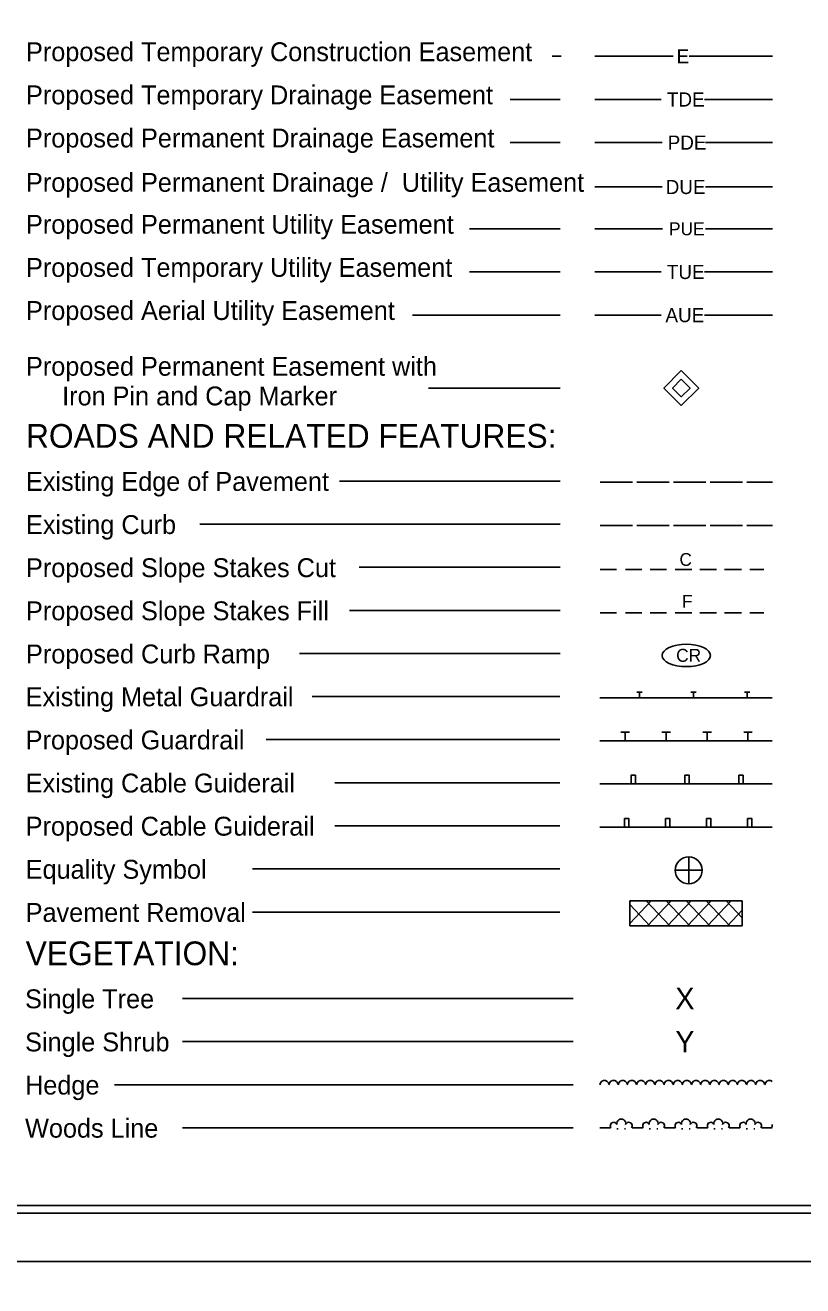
# Model space of a CAD drawing. Extents: x 1664524 to 1666208, y 587901 to 592296.
# Drawn here: x 1665085 to 1665446, y 588990 to 589575 of the extents above; entities that cross this region are included whole.
import ezdxf

# ---------------------------------------------------------------- set-up
doc = ezdxf.new("R2010")
doc.units = 0
for name, color, linetype in [('Prop Easement Permanent Drainage Utility', 7, 'Continuous'), ('Prop Horizontal Alignment Tick Large', 7, 'Continuous'), ('Prop Horizontal Alignment Tick Small', 7, 'Continuous'), ('Prop ROW Permanent Easement CELL', 7, 'Continuous'), ('Prop WCC CELL', 7, 'Continuous'), ('Sheet Cutting Line CELL', 7, 'Continuous'), ('Sheet Symbology CELL', 7, 'Continuous')]:
    doc.layers.add(name, color=color, linetype=linetype)

msp = doc.modelspace()

# ---------------------------------------------------------------- linework, layer by layer
at = {"layer": 'Prop Easement Permanent Drainage Utility'}
for p, q in [((1665349.26, 589499.7), (1665380.56, 589499.7)), ((1665400.56, 589499.7), (1665431.76, 589499.7))]:
    msp.add_line(p, q, dxfattribs=at)
at = {"layer": 'Prop Horizontal Alignment Tick Large'}
msp.add_lwpolyline([(1664536.76, 589023.8), (1666203.26, 589023.8), (1666203.26, 590078.9), (1664536.76, 590078.9)], close=True, dxfattribs=at)
at = {"layer": 'Prop Horizontal Alignment Tick Small'}
for points in [[(1664523.76, 589001.35), (1666207.76, 589001.35), (1666207.76, 590101.35), (1664523.76, 590101.35)], [(1666207.76, 589001.35), (1664523.76, 589001.35), (1664523.76, 587901.35), (1666207.76, 587901.35)]]:
    msp.add_lwpolyline(points, close=True, dxfattribs=at)
at = {"layer": 'Prop ROW Permanent Easement CELL'}
msp.add_line((1665389.4, 589406.46), (1665389.4, 589406.46), dxfattribs=at)
for points in [[(1665389.4, 589414.51), (1665397.46, 589406.45), (1665389.4, 589398.4), (1665381.35, 589406.45)], [(1665389.4, 589410.48), (1665393.43, 589406.45), (1665389.4, 589402.43), (1665385.38, 589406.45)]]:
    msp.add_lwpolyline(points, close=True, dxfattribs=at)
at = {"layer": 'Prop WCC CELL'}
msp.add_ellipse((1665391.72, 589282.43), major_axis=(11.21, 0), ratio=0.462467, dxfattribs=at)
at = {"layer": 'Sheet Cutting Line CELL'}
for p, q in [((1664523.76, 589001.35), (1666207.76, 589001.35)), ((1666207.76, 589001.35), (1664523.76, 589001.35))]:
    msp.add_line(p, q, dxfattribs=at)
at = {"layer": 'Sheet Symbology CELL'}
for p, q in [((1665333.61, 589560.29), (1665329.44, 589560.29)), ((1665349.26, 589560.29), (1665351.87, 589560.29)), ((1665351.87, 589560.29), (1665385.62, 589560.29)), ((1665393.12, 589560.29), (1665426.87, 589560.29)), ((1665426.87, 589560.29), (1665431.76, 589560.29)), ((1665333.23, 589540.29), (1665310.08, 589540.29)), ((1665349.26, 589540.29), (1665352.61, 589540.29)), ((1665352.61, 589540.29), (1665380.11, 589540.29)), ((1665400.11, 589540.29), (1665427.61, 589540.29)), ((1665427.61, 589540.29), (1665431.76, 589540.29)), ((1665333.23, 589520.29), (1665310.08, 589520.29)), ((1665349.26, 589520.29), (1665353.06, 589520.29)), ((1665353.06, 589520.29), (1665380.56, 589520.29)), ((1665400.56, 589520.29), (1665428.06, 589520.29)), ((1665428.06, 589520.29), (1665431.76, 589520.29)), ((1665333.23, 589480.28), (1665291.09, 589480.28)), ((1665349.26, 589480.28), (1665353.1, 589480.28)), ((1665353.1, 589480.28), (1665380.6, 589480.28)), ((1665400.6, 589480.28), (1665428.1, 589480.28)), ((1665428.1, 589480.28), (1665431.76, 589480.28)), ((1665333.23, 589460.28), (1665291.09, 589460.28)), ((1665349.26, 589460.28), (1665352.61, 589460.28)), ((1665352.61, 589460.28), (1665380.11, 589460.28)), ((1665400.11, 589460.28), (1665427.61, 589460.28)), ((1665427.61, 589460.28), (1665431.76, 589460.28)), ((1665333.23, 589440.28), (1665264.77, 589440.28)), ((1665349.26, 589440.28), (1665352.61, 589440.28)), ((1665352.61, 589440.28), (1665380.11, 589440.28)), ((1665400.11, 589440.28), (1665427.61, 589440.28)), ((1665427.61, 589440.28), (1665431.76, 589440.28)), ((1665333.23, 589406.45), (1665272.22, 589406.45)), ((1665333.23, 589363.3), (1665230.88, 589363.3)), ((1665351.76, 589362.72), (1665366.76, 589362.72)), ((1665368.76, 589362.72), (1665383.76, 589362.72)), ((1665385.76, 589362.72), (1665400.76, 589362.72)), ((1665402.76, 589362.72), (1665417.76, 589362.72)), ((1665419.76, 589362.72), (1665431.76, 589362.72)), ((1665333.23, 589343.3), (1665166.08, 589343.3)), ((1665351.76, 589342.72), (1665366.76, 589342.72)), ((1665368.76, 589342.72), (1665383.76, 589342.72)), ((1665385.76, 589342.72), (1665400.76, 589342.72)), ((1665402.76, 589342.72), (1665417.76, 589342.72)), ((1665419.76, 589342.72), (1665431.76, 589342.72)), ((1665333.23, 589323.3), (1665240.04, 589323.3)), ((1665351.76, 589322.25), (1665359.36, 589322.25)), ((1665371.06, 589322.25), (1665363.51, 589322.25)), ((1665382.56, 589322.25), (1665374.96, 589322.25)), ((1665394.31, 589322.25), (1665386.51, 589322.25)), ((1665405.76, 589322.25), (1665398.01, 589322.25)), ((1665417.31, 589322.25), (1665409.46, 589322.25)), ((1665427.61, 589322.25), (1665421.21, 589322.25)), ((1665333.23, 589303.3), (1665235.49, 589303.3)), ((1665351.76, 589302.25), (1665359.36, 589302.25)), ((1665371.06, 589302.25), (1665363.51, 589302.25)), ((1665382.56, 589302.25), (1665374.96, 589302.25)), ((1665394.31, 589302.25), (1665386.51, 589302.25)), ((1665405.76, 589302.25), (1665398.01, 589302.25)), ((1665417.31, 589302.25), (1665409.46, 589302.25)), ((1665427.61, 589302.25), (1665421.21, 589302.25)), ((1665333.23, 589283.3), (1665212.3, 589283.3)), ((1665333.07, 589263.42), (1665218.23, 589263.42)), ((1665351.6, 589262.84), (1665431.6, 589262.84)), ((1665368.74, 589265.34), (1665371.24, 589265.34)), ((1665369.99, 589262.84), (1665369.99, 589265.34)), ((1665393.74, 589265.34), (1665396.24, 589265.34)), ((1665394.99, 589262.84), (1665394.99, 589265.34)), ((1665418.74, 589265.34), (1665421.24, 589265.34)), ((1665419.99, 589262.84), (1665419.99, 589265.34)), ((1665333.07, 589243.42), (1665196.83, 589243.42)), ((1665431.6, 589242.84), (1665351.6, 589242.84)), ((1665361.33, 589246.79), (1665365.33, 589246.79)), ((1665363.33, 589242.84), (1665363.33, 589246.79)), ((1665380.33, 589246.79), (1665384.33, 589246.79)), ((1665382.33, 589242.84), (1665382.33, 589246.79)), ((1665399.33, 589246.79), (1665403.33, 589246.79)), ((1665401.33, 589242.84), (1665401.33, 589246.79)), ((1665418.33, 589246.79), (1665422.33, 589246.79)), ((1665420.33, 589242.84), (1665420.33, 589246.79)), ((1665333.07, 589223.42), (1665228.77, 589223.42)), ((1665351.6, 589222.84), (1665431.6, 589222.84)), ((1665333.07, 589203.42), (1665228.77, 589203.42)), ((1665351.6, 589202.84), (1665431.6, 589202.84)), ((1665392.83, 589189.08), (1665392.83, 589182.83)), ((1665333.07, 589183.42), (1665190.45, 589183.42)), ((1665386.58, 589182.83), (1665392.83, 589182.83)), ((1665392.83, 589182.83), (1665392.83, 589176.58)), ((1665392.83, 589182.83), (1665399.08, 589182.83)), ((1665365.55, 589168.7), (1665417.65, 589168.7)), ((1665365.55, 589157), (1665365.55, 589168.7)), ((1665365.55, 589168.1), (1665366.1, 589168.7)), ((1665365.55, 589158.15), (1665375.4, 589168.7)), ((1665374.8, 589157), (1665365.55, 589166.9)), ((1665384.1, 589157), (1665373.1, 589168.7)), ((1665373.7, 589157), (1665384.7, 589168.7)), ((1665393.35, 589157), (1665382.4, 589168.7)), ((1665382.95, 589157), (1665394, 589168.7)), ((1665402.65, 589157), (1665391.65, 589168.7)), ((1665392.25, 589157), (1665403.25, 589168.7)), ((1665411.95, 589157), (1665400.9, 589168.7)), ((1665401.55, 589157), (1665412.5, 589168.7)), ((1665417.65, 589160.75), (1665410.2, 589168.7)), ((1665417.65, 589168.7), (1665417.65, 589157)), ((1665333.07, 589163.42), (1665190.45, 589163.42)), ((1665410.8, 589157), (1665417.65, 589164.3)), ((1665417.65, 589157), (1665365.55, 589157)), ((1665339.21, 589123.35), (1665158.08, 589123.35)), ((1665339.21, 589103.35), (1665158.08, 589103.35)), ((1665351.9, 589084.3), (1665352.5, 589084.95)), ((1665352.5, 589084.95), (1665353.3, 589085.4)), ((1665353.3, 589085.4), (1665354.25, 589085.4)), ((1665354.25, 589085.4), (1665355.05, 589084.9)), ((1665355.05, 589084.9), (1665355.6, 589084.25)), ((1665356.15, 589084.3), (1665356.75, 589084.95)), ((1665356.75, 589084.95), (1665357.55, 589085.4)), ((1665357.55, 589085.4), (1665358.5, 589085.4)), ((1665358.5, 589085.4), (1665359.3, 589084.9)), ((1665359.3, 589084.9), (1665359.85, 589084.25)), ((1665360.4, 589084.3), (1665361, 589084.95)), ((1665361, 589084.95), (1665361.8, 589085.4)), ((1665361.8, 589085.4), (1665362.75, 589085.4)), ((1665362.75, 589085.4), (1665363.55, 589084.9)), ((1665363.55, 589084.9), (1665364.1, 589084.25)), ((1665364.65, 589084.3), (1665365.25, 589084.95)), ((1665365.25, 589084.95), (1665366.05, 589085.4)), ((1665366.05, 589085.4), (1665367, 589085.4)), ((1665367, 589085.4), (1665367.8, 589084.9)), ((1665367.8, 589084.9), (1665368.35, 589084.25)), ((1665368.9, 589084.3), (1665369.5, 589084.95)), ((1665369.5, 589084.95), (1665370.3, 589085.4)), ((1665370.3, 589085.4), (1665371.25, 589085.4)), ((1665371.25, 589085.4), (1665372.05, 589084.9)), ((1665372.05, 589084.9), (1665372.6, 589084.25)), ((1665373.15, 589084.3), (1665373.75, 589084.95)), ((1665373.75, 589084.95), (1665374.55, 589085.4)), ((1665374.55, 589085.4), (1665375.5, 589085.4)), ((1665375.5, 589085.4), (1665376.3, 589084.9)), ((1665376.3, 589084.9), (1665376.85, 589084.25)), ((1665377.4, 589084.3), (1665378, 589084.95)), ((1665378, 589084.95), (1665378.8, 589085.4)), ((1665378.8, 589085.4), (1665379.75, 589085.4)), ((1665379.75, 589085.4), (1665380.55, 589084.9)), ((1665380.55, 589084.9), (1665381.1, 589084.25)), ((1665381.65, 589084.3), (1665382.25, 589084.95)), ((1665382.25, 589084.95), (1665383.05, 589085.4)), ((1665383.05, 589085.4), (1665384, 589085.4)), ((1665384, 589085.4), (1665384.8, 589084.9)), ((1665384.8, 589084.9), (1665385.35, 589084.25)), ((1665385.9, 589084.3), (1665386.5, 589084.95)), ((1665386.5, 589084.95), (1665387.3, 589085.4)), ((1665387.3, 589085.4), (1665388.25, 589085.4)), ((1665388.25, 589085.4), (1665389.05, 589084.9)), ((1665389.05, 589084.9), (1665389.6, 589084.25)), ((1665390.15, 589084.3), (1665390.75, 589084.95)), ((1665390.75, 589084.95), (1665391.55, 589085.4)), ((1665391.55, 589085.4), (1665392.5, 589085.4)), ((1665392.5, 589085.4), (1665393.3, 589084.9)), ((1665393.3, 589084.9), (1665393.85, 589084.25)), ((1665394.4, 589084.3), (1665395, 589084.95)), ((1665395, 589084.95), (1665395.8, 589085.4)), ((1665395.8, 589085.4), (1665396.75, 589085.4)), ((1665396.75, 589085.4), (1665397.55, 589084.9)), ((1665397.55, 589084.9), (1665398.1, 589084.25)), ((1665398.65, 589084.3), (1665399.25, 589084.95)), ((1665399.25, 589084.95), (1665400.05, 589085.4)), ((1665400.05, 589085.4), (1665401, 589085.4)), ((1665401, 589085.4), (1665401.8, 589084.9)), ((1665401.8, 589084.9), (1665402.35, 589084.25)), ((1665402.9, 589084.3), (1665403.5, 589084.95)), ((1665403.5, 589084.95), (1665404.3, 589085.4)), ((1665404.3, 589085.4), (1665405.25, 589085.4)), ((1665405.25, 589085.4), (1665406.05, 589084.9)), ((1665406.05, 589084.9), (1665406.6, 589084.25)), ((1665407.15, 589084.3), (1665407.75, 589084.95)), ((1665407.75, 589084.95), (1665408.55, 589085.4)), ((1665408.55, 589085.4), (1665409.5, 589085.4)), ((1665409.5, 589085.4), (1665410.3, 589084.9)), ((1665410.3, 589084.9), (1665410.85, 589084.25)), ((1665411.4, 589084.3), (1665412, 589084.95)), ((1665412, 589084.95), (1665412.8, 589085.4)), ((1665412.8, 589085.4), (1665413.75, 589085.4)), ((1665413.75, 589085.4), (1665414.55, 589084.9)), ((1665414.55, 589084.9), (1665415.1, 589084.25)), ((1665415.65, 589084.3), (1665416.25, 589084.95)), ((1665416.25, 589084.95), (1665417.05, 589085.4)), ((1665417.05, 589085.4), (1665418, 589085.4)), ((1665418, 589085.4), (1665418.8, 589084.9)), ((1665418.8, 589084.9), (1665419.35, 589084.25)), ((1665419.9, 589084.3), (1665420.5, 589084.95)), ((1665420.5, 589084.95), (1665421.3, 589085.4)), ((1665421.3, 589085.4), (1665422.25, 589085.4)), ((1665422.25, 589085.4), (1665423.05, 589084.9)), ((1665423.05, 589084.9), (1665423.6, 589084.25)), ((1665424.15, 589084.3), (1665424.75, 589084.95)), ((1665424.75, 589084.95), (1665425.55, 589085.4)), ((1665425.55, 589085.4), (1665426.5, 589085.4)), ((1665426.5, 589085.4), (1665427.3, 589084.9)), ((1665427.3, 589084.9), (1665427.85, 589084.25)), ((1665428.4, 589084.3), (1665429, 589084.95)), ((1665429, 589084.95), (1665429.8, 589085.4)), ((1665429.8, 589085.4), (1665430.75, 589085.4)), ((1665430.75, 589085.4), (1665431.55, 589084.9)), ((1665431.55, 589084.9), (1665431.6, 589084.85)), ((1665339.21, 589083.35), (1665126.52, 589083.35)), ((1665351.6, 589083.35), (1665351.9, 589084.3)), ((1665355.6, 589084.25), (1665355.8, 589083.4)), ((1665355.85, 589083.35), (1665356.15, 589084.3)), ((1665359.85, 589084.25), (1665360.05, 589083.4)), ((1665360.1, 589083.35), (1665360.4, 589084.3)), ((1665364.1, 589084.25), (1665364.3, 589083.4)), ((1665364.35, 589083.35), (1665364.65, 589084.3)), ((1665368.35, 589084.25), (1665368.55, 589083.4)), ((1665368.6, 589083.35), (1665368.9, 589084.3)), ((1665372.6, 589084.25), (1665372.8, 589083.4)), ((1665372.85, 589083.35), (1665373.15, 589084.3)), ((1665376.85, 589084.25), (1665377.05, 589083.4)), ((1665377.1, 589083.35), (1665377.4, 589084.3)), ((1665381.1, 589084.25), (1665381.3, 589083.4)), ((1665381.35, 589083.35), (1665381.65, 589084.3)), ((1665385.35, 589084.25), (1665385.55, 589083.4)), ((1665385.6, 589083.35), (1665385.9, 589084.3)), ((1665389.6, 589084.25), (1665389.8, 589083.4)), ((1665389.85, 589083.35), (1665390.15, 589084.3)), ((1665393.85, 589084.25), (1665394.05, 589083.4)), ((1665394.1, 589083.35), (1665394.4, 589084.3)), ((1665398.1, 589084.25), (1665398.3, 589083.4)), ((1665398.35, 589083.35), (1665398.65, 589084.3)), ((1665402.35, 589084.25), (1665402.55, 589083.4)), ((1665402.6, 589083.35), (1665402.9, 589084.3)), ((1665406.6, 589084.25), (1665406.8, 589083.4)), ((1665406.85, 589083.35), (1665407.15, 589084.3)), ((1665410.85, 589084.25), (1665411.05, 589083.4)), ((1665411.1, 589083.35), (1665411.4, 589084.3)), ((1665415.1, 589084.25), (1665415.3, 589083.4)), ((1665415.35, 589083.35), (1665415.65, 589084.3)), ((1665419.35, 589084.25), (1665419.55, 589083.4)), ((1665419.6, 589083.35), (1665419.9, 589084.3)), ((1665423.6, 589084.25), (1665423.8, 589083.4)), ((1665423.85, 589083.35), (1665424.15, 589084.3)), ((1665427.85, 589084.25), (1665428.05, 589083.4)), ((1665428.1, 589083.35), (1665428.4, 589084.3)), ((1665339.21, 589063.35), (1665158.08, 589063.35)), ((1665351.6, 589063.35), (1665356.6, 589063.35)), ((1665359.55, 589062.85), (1665360.05, 589062.85)), ((1665363.05, 589062.85), (1665363.55, 589062.85)), ((1665366.6, 589063.35), (1665371.6, 589063.35)), ((1665374.55, 589062.85), (1665375.05, 589062.85)), ((1665378.05, 589062.85), (1665378.55, 589062.85)), ((1665381.6, 589063.35), (1665386.6, 589063.35)), ((1665389.55, 589062.85), (1665390.05, 589062.85)), ((1665393.05, 589062.85), (1665393.55, 589062.85)), ((1665396.6, 589063.35), (1665401.6, 589063.35)), ((1665404.55, 589062.85), (1665405.05, 589062.85)), ((1665408.05, 589062.85), (1665408.55, 589062.85)), ((1665411.6, 589063.35), (1665416.6, 589063.35)), ((1665419.55, 589062.85), (1665420.05, 589062.85)), ((1665423.05, 589062.85), (1665423.55, 589062.85)), ((1665426.6, 589063.35), (1665431.6, 589063.35))]:
    msp.add_line(p, q, dxfattribs=at)
for points in [[(1666190.76, 590076.35), (1664690.76, 590076.35), (1664690.76, 589027.37), (1666190.76, 589027.37)], [(1665366.08, 589222.84), (1665368.08, 589222.84), (1665368.08, 589226.84), (1665366.08, 589226.84)], [(1665391.08, 589222.84), (1665393.08, 589222.84), (1665393.08, 589226.84), (1665391.08, 589226.84)], [(1665416.08, 589222.84), (1665418.08, 589222.84), (1665418.08, 589226.84), (1665416.08, 589226.84)], [(1665363.06, 589206.84), (1665365.06, 589206.84), (1665365.06, 589202.84), (1665363.06, 589202.84)], [(1665382.06, 589206.84), (1665384.06, 589206.84), (1665384.06, 589202.84), (1665382.06, 589202.84)], [(1665401.06, 589206.84), (1665403.06, 589206.84), (1665403.06, 589202.84), (1665401.06, 589202.84)], [(1665420.06, 589206.84), (1665422.06, 589206.84), (1665422.06, 589202.84), (1665420.06, 589202.84)]]:
    msp.add_lwpolyline(points, close=True, dxfattribs=at)
for centre, radius, start, end in [((1665392.83, 589182.83), 6.25, 89.99439, 179.99893), ((1665392.83, 589182.83), 6.25, 359.99439, 89.99893), ((1665392.83, 589182.83), 6.25, 179.99439, 269.99892), ((1665392.83, 589182.83), 6.25, 269.99439, 359.99893), ((1665361.55, 589065.36), 2.06, 345.96376, 194.03624), ((1665376.55, 589065.36), 2.06, 345.96376, 194.03624), ((1665391.55, 589065.36), 2.06, 345.96376, 194.03624), ((1665406.55, 589065.36), 2.06, 345.96376, 194.03624), ((1665421.55, 589065.36), 2.06, 345.96376, 194.03624), ((1665358.05, 589064.36), 1.58, 18.43495, 219.23152), ((1665365.05, 589064.36), 1.58, 320.76848, 161.56505), ((1665373.05, 589064.36), 1.58, 18.43495, 219.23152), ((1665380.05, 589064.36), 1.58, 320.76848, 161.56505), ((1665388.05, 589064.36), 1.58, 18.43495, 219.23152), ((1665395.05, 589064.36), 1.58, 320.76848, 161.56505), ((1665403.05, 589064.36), 1.58, 18.43495, 219.23152), ((1665410.05, 589064.36), 1.58, 320.76848, 161.56505), ((1665418.05, 589064.36), 1.58, 18.43495, 219.23152), ((1665425.05, 589064.36), 1.58, 320.76848, 161.56505), ((1665433.05, 589064.36), 1.58, 156.25102, 203.74899)]:
    msp.add_arc(centre, radius, start, end, dxfattribs=at)

# ---------------------------------------------------------------- texts
at = {"layer": 'Prop Easement Permanent Drainage Utility'}
msp.add_text('DUE', height=6.55, dxfattribs=at).set_placement((1665382.15, 589496.4))
at = {"layer": 'Prop WCC CELL'}
msp.add_text('CR', height=6, dxfattribs=at).set_placement((1665387.01, 589279.48))
at = {"layer": 'Sheet Symbology CELL'}
for s, height, p in [('Proposed Temporary Construction Easement', 8.75, (1665085.48, 589558.02)), ('E', 6.55, (1665387.22, 589556.99)), ('Proposed Temporary Drainage Easement', 8.75, (1665085.48, 589538.02)), ('TDE', 6.55, (1665382.71, 589536.99)), ('Proposed Permanent Drainage Easement', 8.75, (1665085.48, 589518.02)), ('PDE', 6.55, (1665383.06, 589516.99)), ('Proposed Permanent Drainage /  Utility Easement', 8.75, (1665085.48, 589497.44)), ('Proposed Permanent Utility Easement', 8.75, (1665085.48, 589478.01)), ('PUE', 6, (1665383.7, 589477.28)), ('Proposed Temporary Utility Easement', 8.75, (1665085.48, 589458.01)), ('TUE', 6.55, (1665382.69, 589456.98)), ('Proposed Aerial Utility Easement', 8.75, (1665085.48, 589438.01)), ('AUE', 6.55, (1665382.03, 589436.98)), ('Proposed Permanent Easement with', 8.75, (1665085.48, 589412.15)), ('Iron Pin and Cap Marker', 8.75, (1665102.24, 589398.4)), ('ROADS AND RELATED FEATURES:', 11, (1665085.48, 589378.75)), ('Existing Edge of Pavement', 8.75, (1665085.48, 589358.75)), ('Existing Curb', 8.75, (1665085.48, 589338.75)), ('Proposed Slope Stakes Cut', 8.75, (1665085.48, 589318.75)), ('C', 5.93, (1665388.56, 589323.98)), ('Proposed Slope Stakes Fill', 8.75, (1665085.48, 589298.75)), ('F', 5.93, (1665389.76, 589304.61)), ('Proposed Curb Ramp', 8.75, (1665085.48, 589278.75)), ('Existing Metal Guardrail', 8.75, (1665085.32, 589258.87)), ('Proposed Guardrail', 8.75, (1665085.33, 589238.88)), ('Existing Cable Guiderail', 8.75, (1665085.33, 589218.88)), ('Proposed Cable Guiderail', 8.75, (1665085.33, 589198.88)), ('Equality Symbol', 8.75, (1665085.33, 589178.88)), ('Pavement Removal', 8.75, (1665085.33, 589158.88)), ('VEGETATION:', 11, (1665085.32, 589138.8)), ('Single Tree', 8.75, (1665085.05, 589118.82)), ('X', 10, (1665386.6, 589118.35)), ('Y', 10, (1665386.6, 589098.35)), ('Single Shrub', 8.75, (1665085.05, 589098.82)), ('Hedge', 8.75, (1665085.05, 589078.82)), ('Woods Line', 8.75, (1665085.05, 589058.82))]:
    msp.add_text(s, height=height, dxfattribs=at).set_placement(p)

doc.saveas('drawing.dxf')
